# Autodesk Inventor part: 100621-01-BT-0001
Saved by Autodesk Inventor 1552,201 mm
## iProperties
Created: 2010-06
Part Number: 100621-01-BT-0001
Material: Standard
Document SubType Name: Blech
Designer: MP
Density: 1 g/cm^3
Flat Pattern Width: 155.22 cm
Flat Pattern Length: 152.058 cm
Flat Pattern Area: 23602.5 cm^2
Sheet Metal Rule: Standard_mm
Sheet Metal Width: 1520,581 mm
Sheet Metal Length: 2360247,915 mm^2
Author: MP
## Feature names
1. Biegung1
